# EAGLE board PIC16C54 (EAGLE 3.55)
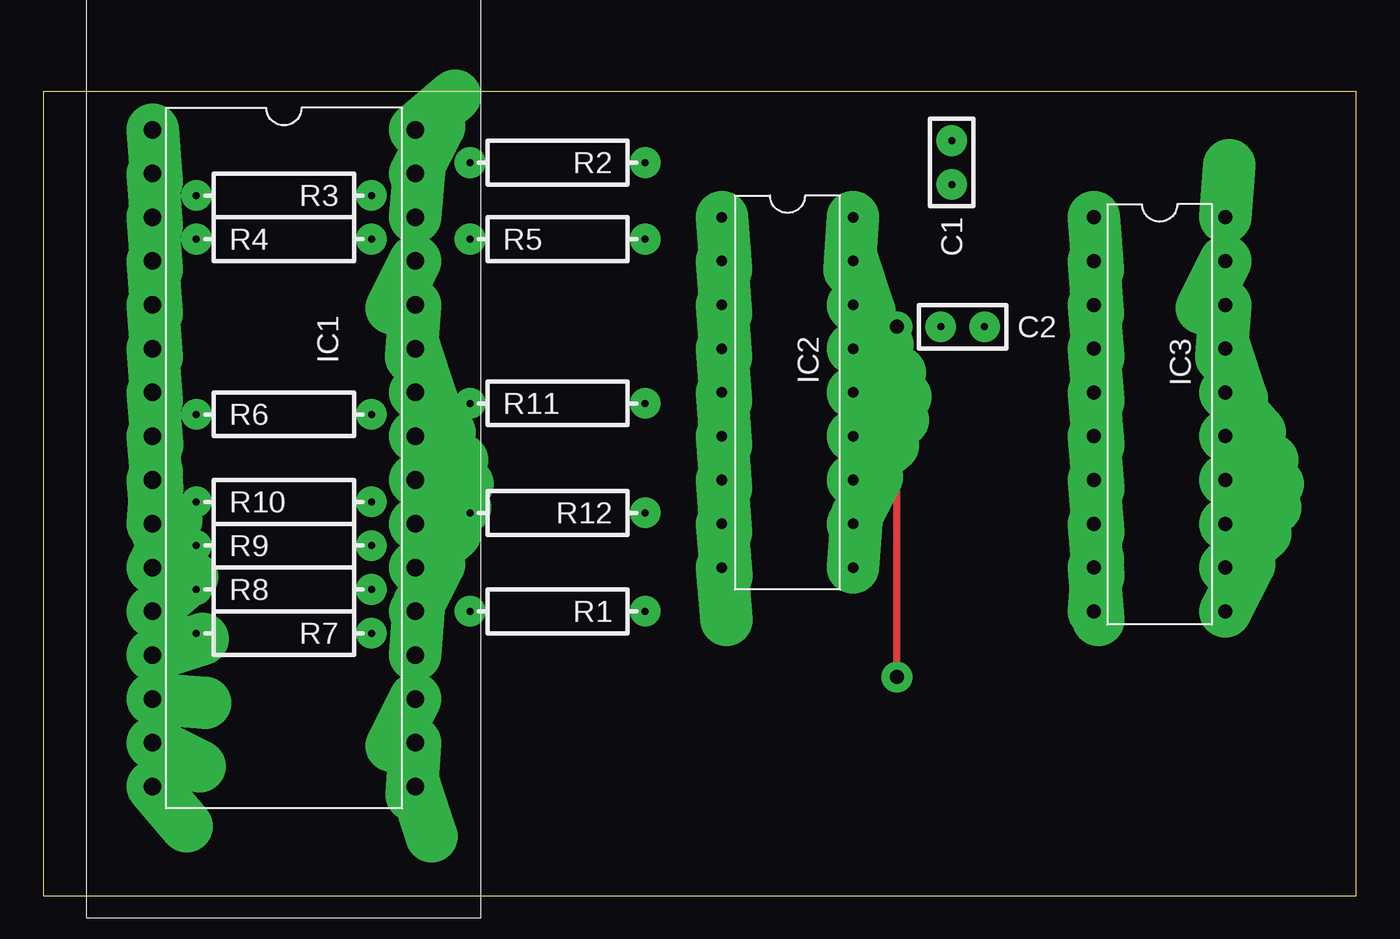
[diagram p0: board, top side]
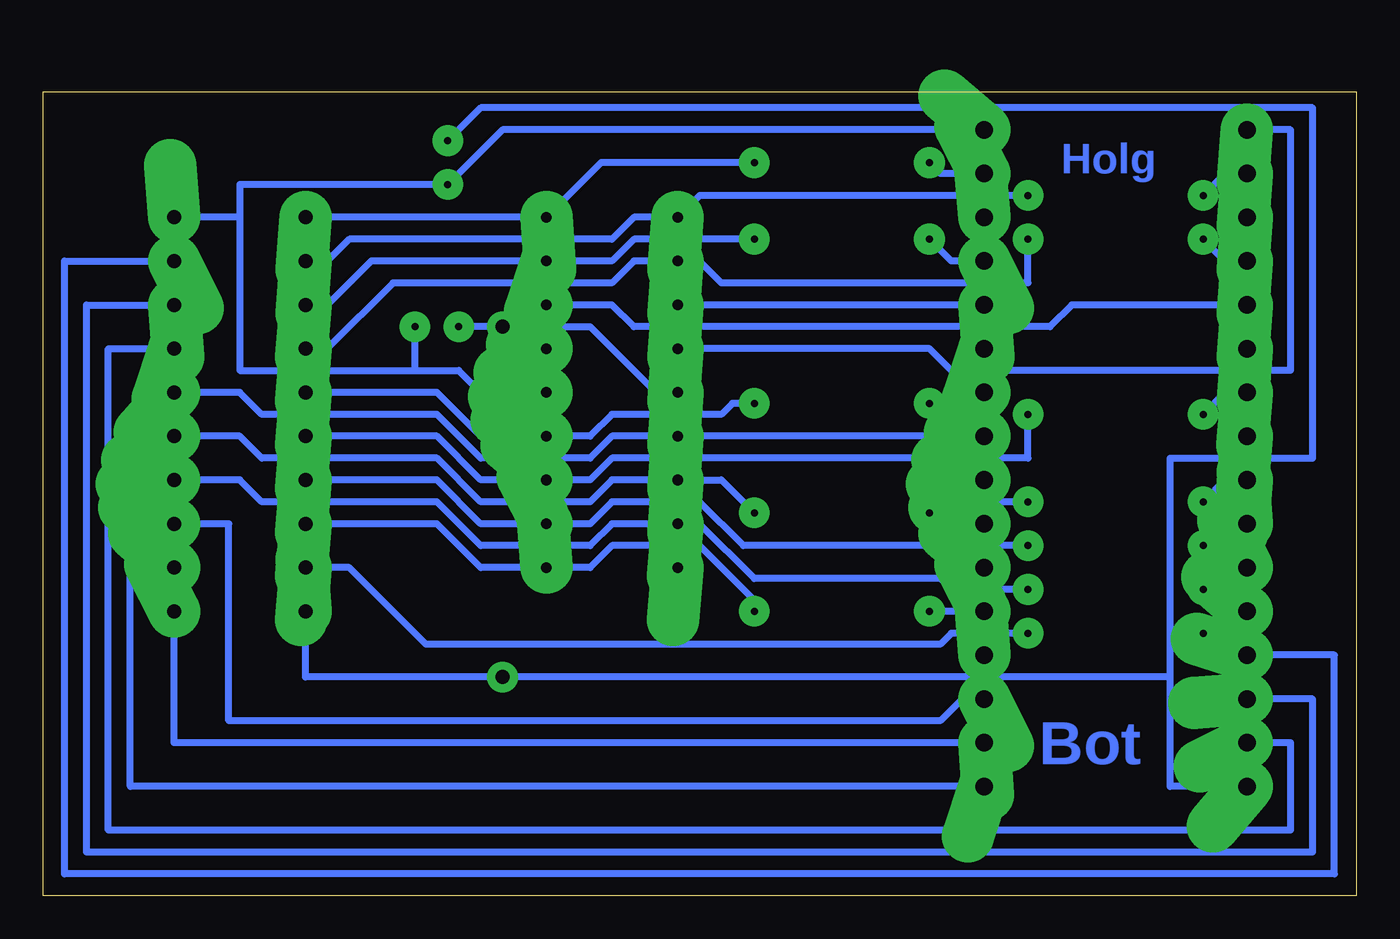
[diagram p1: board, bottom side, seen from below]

Size 76.18 x 46.66 mm. Coordinates in mm from the lower left corner, seen from the top.
Outline: 0,0 76.18,0 76.18,46.66 0,46.66 0,0
Copper layers used: Top, Bottom

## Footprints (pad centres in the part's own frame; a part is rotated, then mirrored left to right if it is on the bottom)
RM2,5 = drill 0.406 pad 1.778 round:  0,0;  2.54,0
XTO_32 = drill 1.016 pad 3.048 offset:  0,0;  2.54,0;  15.24,0;  17.78,0;  5.08,0;  7.62,0;  12.7,0;  10.16,0;  20.32,0;  22.86,0;  25.4,0;  27.94,0;  30.48,0;  33.02,0;  35.56,0;  38.1,0;  38.1,15.24;  35.56,15.24;  33.02,15.24;  30.48,15.24;  27.94,15.24;  25.4,15.24;  22.86,15.24;  20.32,15.24;  17.78,15.24;  15.24,15.24;  12.7,15.24;  10.16,15.24;  7.62,15.24;  5.08,15.24;  2.54,15.24;  0,15.24
L-18B = drill 0.61 pad 3.048 offset:  0,0;  2.54,0;  15.24,0;  17.78,0;  5.08,0;  7.62,0;  12.7,0;  10.16,0;  20.32,0;  20.32,7.62;  17.78,7.62;  15.24,7.62;  12.7,7.62;  10.16,7.62;  7.62,7.62;  5.08,7.62;  2.54,7.62;  0,7.62
L-20B = drill 0.813 pad 3.048 offset:  0,0;  2.54,0;  5.08,0;  7.62,0;  10.16,0;  12.7,0;  15.24,0;  17.78,0;  20.32,0;  22.86,0;  22.86,7.62;  20.32,7.62;  17.78,7.62;  15.24,7.62;  12.7,7.62;  10.16,7.62;  7.62,7.62;  5.08,7.62;  2.54,7.62;  0,7.62
S04 = drill 0.406 pad 1.778 round:  0,0;  10.16,0

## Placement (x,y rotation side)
C1  C100NK  [RM2,5]  52.7,43.81 270 top
C2  C100NK  [RM2,5]  52.07,33.02 0 top
IC1  Sockel1  [XTO_32]  6.35,44.45 270 top
IC2  16C54P  [L-18B]  39.37,39.37 270 top
IC3  GAL16V8  [L-20B]  60.96,39.37 270 top
R1  4k7  [S04]  34.92,16.51 180 top
R2  4k7  [S04]  34.92,42.55 180 top
R3  4k7  [S04]  19.05,40.64 180 top
R4  4k7  [S04]  8.89,38.1 0 top
R5  4k7  [S04]  24.77,38.1 0 top
R6  4k7  [S04]  8.89,27.94 0 top
R7  4k7  [S04]  19.05,15.24 180 top
R8  4k7  [S04]  8.89,17.78 0 top
R9  4k7  [S04]  8.89,20.32 0 top
R10  4k7  [S04]  8.89,22.86 0 top
R11  4k7  [S04]  24.77,28.57 0 top
R12  4k7  [S04]  34.92,22.23 180 top

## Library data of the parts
C1 C2 IC2 R1-R12 = holg_plt
IC1 IC3 = galeprom

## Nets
+5V: C1. C2. IC1. IC2. IC3.
A0: IC2. IC3. R7.
A1: IC2. IC3. R8.
A2: IC2. IC3. R9.
A3: IC2. IC3. R10.
A5: IC2. IC3. R6.
A7: IC1. IC2.
A10: IC2. IC3. R12.
A11: IC2. IC3. R11.
A12: IC2. IC3. R4.
A13: IC1. IC2.
A14: IC2. IC3. R5.
A16: IC2. IC3. R3.
A18: IC2. IC3. R2.
D0: IC1. IC3.
D1: IC1. IC3.
D2: IC1. IC3.
D3: IC1. IC3.
D4: IC1. IC3.
D5: IC1. IC3.
D7: IC2. IC3. R1.
GND: C1. C2. IC1. IC2. IC3.
N$1: IC1. R1.
N$2: IC1. R2.
N$3: IC1. R3.
N$4: IC1. R4.
N$5: IC1. R5.
N$6: IC1. R6.
N$7: IC1. R7.
N$8: IC1. R8.
N$9: IC1. R9.
N$10: IC1. R10.
N$11: IC1. R11.
N$12: IC1. R12.
VPP: IC1. IC2.

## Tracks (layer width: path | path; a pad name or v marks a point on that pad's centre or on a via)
+5V
  Bottom 0.406: 46.99,29.21 50.8,29.21 52.07,30.48 54.61,30.48 | 54.61,30.48 64.77,30.48 64.77,39.37 | 64.77,39.37 IC3. | 54.61,30.48 C2. | IC1. 49.53,44.45 C1. 64.77,41.27 64.77,39.37
A0
  Bottom 0.406: 39.37,14.61 24.13,14.61 23.5,15.24 19.05,15.24 | 39.37,14.61 39.37,19.05 | 39.37,14.61 53.98,14.61 58.42,19.05 60.96,19.05
A1
  Bottom 0.406: 68.58,24.13 64.77,24.13 63.5,22.86 53.34,22.86 50.8,20.32 44.45,20.32 43.18,21.59 39.37,21.59 38.1,21.59 34.92,18.41 24.13,18.41 23.5,17.78 R8.
A2
  Bottom 0.406: 60.96,24.13 53.34,24.13 50.8,21.59 46.99,21.59 44.45,21.59 43.18,22.86 38.1,22.86 35.56,20.32 R9.
A3
  Bottom 0.406: 60.96,26.67 53.34,26.67 50.8,24.13 46.99,24.13 44.45,24.13 43.18,25.4 25.4,25.4 22.86,22.86 R10.
A5
  Bottom 0.406: 68.58,29.21 64.77,29.21 63.5,27.94 53.34,27.94 50.8,25.4 44.45,25.4 43.18,26.67 39.37,26.67 24.77,26.67 23.5,25.4 19.05,25.4 R6.
A7
  Bottom 0.406: 6.35,34.29 16.51,34.29 17.78,33.02 41.91,33.02 43.18,34.29 46.99,34.29
A10
  Bottom 0.406: 68.58,26.67 64.77,26.67 63.5,25.4 53.34,25.4 50.8,22.86 44.45,22.86 43.18,24.13 39.37,24.13 36.83,24.13 34.92,22.23
A11
  Bottom 0.406: 60.96,29.21 53.34,29.21 50.8,26.67 46.99,26.67 44.45,26.67 43.18,27.94 36.83,27.94 36.2,28.57 R11.
A12
  Bottom 0.406: 60.96,31.75 59.69,31.75 55.88,35.56 43.18,35.56 41.91,36.83 39.37,36.83 38.1,36.83 36.83,35.56 19.05,35.56 R4.
A13
  Bottom 0.406: 21.59,34.29 39.37,34.29
A14
  Bottom 0.406: 60.96,34.29 59.69,34.29 57.15,36.83 46.99,36.83 43.18,36.83 41.91,38.1 R5.
A16
  Bottom 0.406: 60.96,36.83 59.69,36.83 58.42,38.1 43.18,38.1 41.91,39.37 39.37,39.37 38.1,40.64 19.05,40.64
A18
  Bottom 0.406: 60.96,39.37 IC2. 43.81,42.55 34.92,42.55
D0
  Bottom 0.406: 6.35,13.97 1.27,13.97 1.27,1.27 74.93,1.27 74.93,36.83 68.58,36.83
D1
  Bottom 0.406: 6.35,11.43 2.54,11.43 2.54,2.54 73.66,2.54 73.66,34.29 68.58,34.29
D2
  Bottom 0.406: 6.35,8.89 3.81,8.89 3.81,3.81 72.39,3.81 72.39,31.75 68.58,31.75
D3
  Bottom 0.406: 21.59,6.35 71.12,6.35 71.12,19.05 68.58,19.05
D4
  Bottom 0.406: 21.59,8.89 68.58,8.89 68.58,16.51
D5
  Bottom 0.406: 21.59,11.43 22.86,11.43 24.13,10.16 65.41,10.16 65.41,21.59 68.58,21.59
D7
  Bottom 0.406: 60.96,21.59 53.34,21.59 50.8,19.05 46.99,19.05 44.45,19.05 43.18,20.32 38.1,20.32 34.92,17.14 34.92,16.51
GND  (via drill 0.81 pad 1.78)
  Top 0.406: v49.53,12.7 v49.53,33.02
  Bottom 0.406: 6.35,6.35 10.79,6.35 10.79,12.7 | 10.79,12.7 v49.53,12.7 60.96,12.7 60.96,16.51 | 10.79,12.7 10.79,25.4 2.54,25.4 2.54,45.72 50.8,45.72 52.7,43.81 | 39.37,29.21 40.64,29.21 44.45,33.02 v49.53,33.02 | v49.53,33.02 52.07,33.02 v49.53,33.02
N$1
  Bottom 0.406: 21.59,16.51 R1.
N$2
  Bottom 0.406: 21.59,41.91 24.13,41.91 R2.
N$3
  Bottom 0.406: 6.35,41.91 7.62,41.91 R3.
N$4
  Bottom 0.406: 6.35,36.83 7.62,36.83 8.89,38.1
N$5
  Bottom 0.406: 21.59,36.83 23.5,36.83 24.77,38.1
N$6
  Bottom 0.406: 6.35,29.21 7.62,29.21 8.89,27.94
N$7
  Bottom 0.406: 6.35,16.51 7.62,16.51 R7.
N$8
  Bottom 0.406: 6.35,19.05 7.62,19.05 8.89,17.78
N$9
  Bottom 0.406: 6.35,21.59 7.62,21.59 8.89,20.32
N$10
  Bottom 0.406: 6.35,24.13 7.62,24.13 8.89,22.86
N$11
  Bottom 0.406: 21.59,26.67 22.86,26.67 24.77,28.57
N$12
  Bottom 0.406: 21.59,21.59 24.13,21.59 R12.
VPP
  Bottom 0.406: 6.35,44.45 3.81,44.45 3.81,30.48 23.5,30.48 24.77,31.75 39.37,31.75

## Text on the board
Bottom: Holg | Bot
